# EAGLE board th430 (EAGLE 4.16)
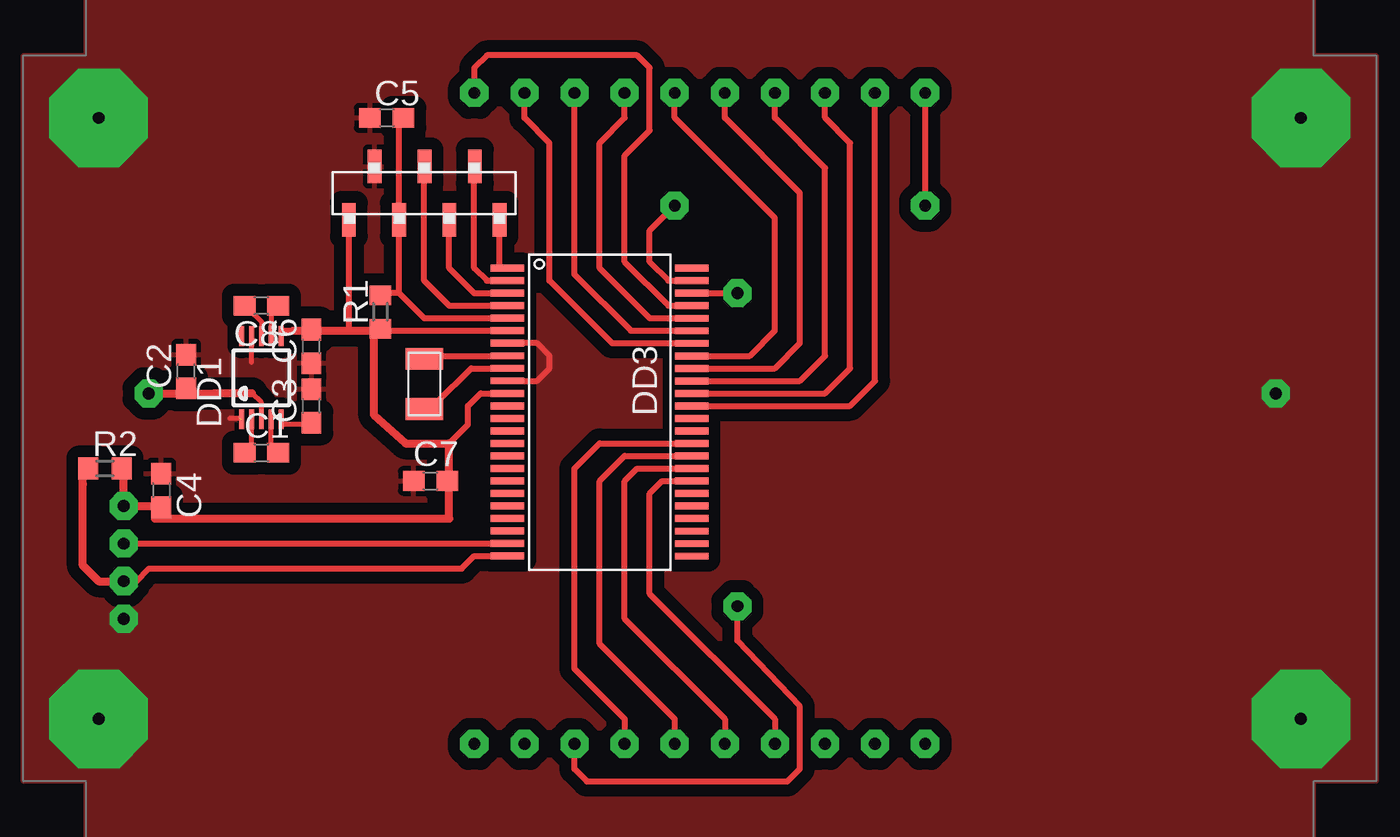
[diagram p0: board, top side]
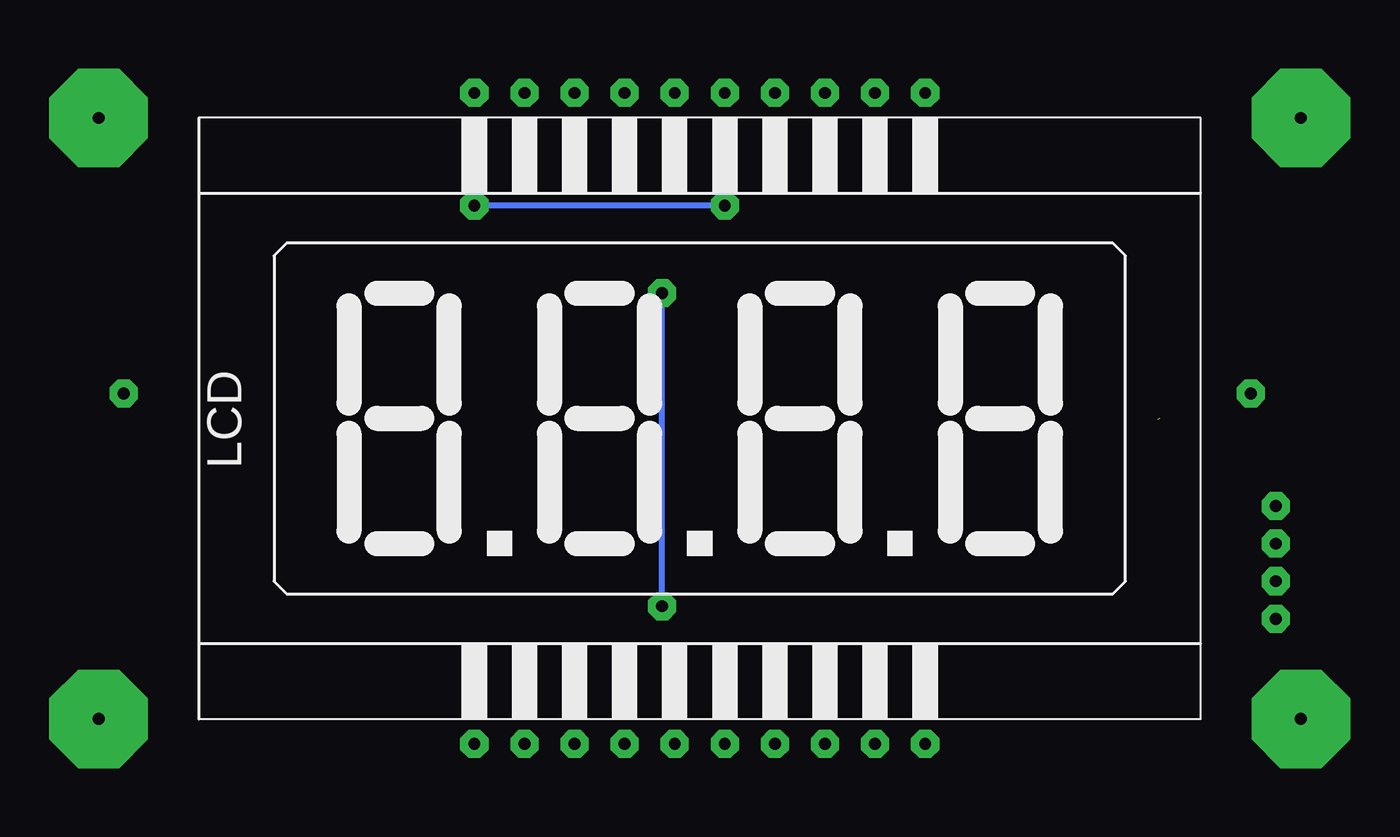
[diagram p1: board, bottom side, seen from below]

No outline drawn. Coordinates in mm, seen from the top.
Copper layers (1*16): Top 0.035mm / dielectric 1.5mm / Bottom 0.035mm
Design rules "default": minimum track width 10mil, minimum drill 24mil, track to track 8mil, track to pad 8mil, pad to pad 8mil, via to via 8mil, smd to smd 8mil, copper to edge 40mil, drill to drill 8mil, minimum pad ring 10mil, minimum via ring 8mil, stop-mask expansion 4mil, vias tented up to drill 0mil, thermal gap 10mil

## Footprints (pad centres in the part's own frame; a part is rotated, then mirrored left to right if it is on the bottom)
C0603 = smd 1.1 x 1: 1 -0.85,0; 2 0.85,0
MSOP10 = smd 0.25 x 1: 1 -1,-2.113; 2 -0.5,-2.113; 3 0,-2.113; 4 0.5,-2.113; 5 1,-2.113; 6 1,2.113; 7 0.5,2.113; 8 0,2.113; 9 -0.5,2.113; 10 -1,2.113
DL48 = smd 0.35 x 1.705: 1 -7.305,-4.67; 2 -6.67,-4.67; 3 -6.035,-4.67; 4 -5.4,-4.67; 5 -4.765,-4.67; 6 -4.13,-4.67; 7 -3.495,-4.67; 8 -2.86,-4.67; 9 -2.225,-4.67; 10 -1.59,-4.67; 11 -0.955,-4.67; 12 -0.32,-4.67; 13 0.315,-4.67; 14 0.95,-4.67; 15 1.585,-4.67; 16 2.22,-4.67; 17 2.855,-4.67; 18 3.49,-4.67; 19 4.125,-4.67; 20 4.76,-4.67; 21 5.395,-4.67; 22 6.03,-4.67; 23 6.665,-4.67; 24 7.3,-4.67; 25 7.305,4.67; 26 6.67,4.67; 27 6.035,4.67; 28 5.4,4.67; 29 4.765,4.67; 30 4.13,4.67; 31 3.495,4.67; 32 2.86,4.67; 33 2.225,4.67; 34 1.59,4.67; 35 0.955,4.67; 36 0.32,4.67; 37 -0.315,4.67; 38 -0.95,4.67; 39 -1.585,4.67; 40 -2.22,4.67; 41 -2.855,4.67; 42 -3.49,4.67; 43 -4.125,4.67; 44 -4.76,4.67; 45 -5.395,4.67; 46 -6.03,4.67; 47 -6.665,4.67; 48 -7.3,4.67
VIM404 = drill 0.6 pad 1.422 octagon: 1 -11.43,-16.51; 2 -8.89,-16.51; 3 -6.35,-16.51; 4 -3.81,-16.51; 5 -1.27,-16.51; 6 1.27,-16.51; 7 3.81,-16.51; 8 6.35,-16.51; 9 8.89,-16.51; 10 11.43,-16.51; 11 11.43,16.51; 12 8.89,16.51; 13 6.35,16.51; 14 3.81,16.51; 15 1.27,16.51; 16 -1.27,16.51; 17 -3.81,16.51; 18 -6.35,16.51; 19 -8.89,16.51; 20 -11.43,16.51
ABS07 = smd 1.1 x 1.9: 1 -1.27,0; 2 1.27,0
HEADER7S = smd 0.7 x 1.7: P$1 -1.27,1.35; P$2 1.28,1.35; P$3 -3.82,1.35; P$4 -2.57,-1.35; P$5 -0.02,-1.35; P$6 3.82,1.35; P$7 2.52,-1.35
R0603 = smd 1 x 1.1: 1 -0.85,0; 2 0.85,0

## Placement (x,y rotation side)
C1  [C0603]  12.06,19.84 0 top
C2  [C0603]  8.26,23.97 90 top
C3  [C0603]  14.61,22.22 90 top
C4  [C0603]  6.99,17.94 270 top
C5  [C0603]  18.41,36.83 0 top
C6  [C0603]  14.61,25.24 90 top
C7  [C0603]  20.64,18.41 0 top
C8  [C0603]  12.06,27.3 180 top
DD1  [MSOP10]  12.06,23.65 0 top
DD3  [DL48]  29.21,21.91 270 top
E$2  [VIM404]  34.29,21.59 0 bottom
E$11  [ABS07]  20.32,23.34 90 top
E$14  [HEADER7S]  20.32,33.02 180 top
R1  [R0603]  18.1,26.99 90 top
R2  [R0603]  4.13,19.05 0 top

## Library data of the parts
C1-C4 C6-C8 = ref-packages
C5 R1 R2 = smd-ipc
DD1 = analog-devices
DD3 = TI_MSP430_v122
E$2 = display-lcd
E$11 = crystal
E$14 = sb

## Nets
GND: C2.2 C3.2 C4.1 C5.1 C6.1 C7.1 DD1.1 E$14.P$7
S$6: E$2.8
S$13: E$2.11
S$35: E$2.20

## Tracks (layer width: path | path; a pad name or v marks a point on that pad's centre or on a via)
GND  (via drill 0.6 pad 1.42, 0.6 pad 5)  (1 unrouted)
  Top 0.254: 10.95,21.59 10.48,21.59 | 11.56,24.44 11.56,25.4
  Top 0.305: 25.08,25.4 26.04,25.4 26.67,24.77 26.67,24.13 26.04,23.5 24.77,23.5
  other vias: 5.08,11.43 63.5,22.86 3.81,36.83 3.81,6.35 64.77,6.35 64.77,36.83
  pour Top (isolate 0.61): 3.17,3.17 0,3.17 0,40.01 3.17,40.01 3.17,43.18 65.41,43.18 65.41,40.01 68.58,40.01 68.58,3.17 65.4,3.17 65.41,0 3.17,0
S$1
  Top 0.305: 5.08,13.34 5.71,13.34 6.35,13.97 22.23,13.97 22.86,14.61 24.13,14.61
S$2
  Top 0.305: 5.08,15.24 24.13,15.24
S$3  (via drill 0.6 pad 1.42)
  Top 0.406: v6.35,22.86 9.68,22.86
S$4
  Top 0.305: 21.59,31.75 21.59,29.21 22.86,27.94 24.13,27.94
S$5
  Top 0.305: 20.64,24.77 24.13,24.77
S$6
  Top 0.305: 36.2,12.06 36.2,10.32 39.37,6.99 39.37,3.81 38.73,3.17 28.57,3.17 27.94,3.81 E$2.8
S$7
  Top 0.305: 24.13,31.59 24.13,29.21 24.77,29.21
S$8  (via drill 0.6 pad 1.42)
  Top 0.406: 3.81,13.34 | 3.81,13.34 3.02,14.13 3.02,18.26 3.02,19.21 | 3.02,19.21 | 3.81,13.34 v5.08,13.34
S$9
  Top 0.305: 24.77,28.57 23.5,28.57 22.86,29.21 22.86,34.29
S$10
  Top 0.305: 20.32,34.29 20.32,28.57 21.59,27.3 24.77,27.3
S$11
  Top 0.305: 20.95,22.23 20.95,22.38 22.7,24.13 23.81,24.13
S$12
  Top 0.305: 21.59,20.32 22.54,21.27 22.54,22.23 23.18,22.86 23.81,22.86
  Top 0.406: 17.78,26.04 17.78,21.75 19.37,20.32 21.59,20.32
S$13
  Top 0.305: 33.34,27.3 32.7,27.3 30.48,29.53 30.48,34.92 31.75,36.2 31.75,39.37 31.11,40.01 23.5,40.01 22.86,39.37 E$2.11
S$14  (via drill 0.6 pad 1.42)
  other vias: 5.08,15.24
S$15  (via drill 0.6 pad 1.42)
  other vias: 33.02,32.38
S$16
  Top 0.305: 19.05,27.94 18.1,27.94 | 19.05,27.94 20.32,26.67 24.45,26.67 | 19.05,27.94 19.05,36.83
S$17  (via drill 0.6 pad 1.42)
  other vias: 36.2,27.94
S$18
  Top 0.305: 43.18,38.1 43.18,23.5 41.91,22.23 34.29,22.23
S$19
  Top 0.406: 5.08,17.14 5.08,19.05
S$20
  Top 0.305: 30.48,38.1 30.48,36.83 29.21,35.56 29.21,29.21 31.75,26.67 33.34,26.67
S$21
  Top 0.305: 40.64,38.1 40.64,36.83 41.91,35.56 41.91,24.13 40.64,22.86 34.29,22.86
S$22
  Top 0.305: 38.1,38.1 38.1,36.83 40.64,34.29 40.64,24.77 39.37,23.5 34.29,23.5
S$23
  Top 0.305: 34.29,24.13 38.1,24.13 39.37,25.4 39.37,33.02 35.56,36.83 35.56,38.1
S$24
  Top 0.305: 33.02,38.1 33.02,36.83 38.1,31.75 38.1,26.04 36.83,24.77 34.29,24.77
S$25
  Top 0.305: 33.02,5.08 33.02,6.35 29.21,10.16 29.21,18.41 30.48,19.68 33.34,19.68
S$26
  Top 0.305: 35.56,5.08 35.56,6.35 30.48,11.43 30.48,18.41 31.11,19.05 33.34,19.05
S$27
  Top 0.305: 17.62,26.04 24.77,26.04
  Top 0.406: 13.65,26.04 17.62,26.04
S$28
  Top 0.305: 34.29,20.32 29.21,20.32 27.94,19.05 27.94,8.89 30.48,6.35 30.48,5.08
S$29  (via drill 0.6 pad 1.42)
  other vias: 45.72,32.38
S$30
  Top 0.305: 38.1,5.08 38.1,6.35 31.75,12.7 31.75,17.78 32.38,18.41 33.34,18.41
S$31  (via drill 0.6 pad 1.42)
  other vias: 36.2,12.06
S$32
  Top 0.305: 33.02,28.57 32.7,28.57 31.75,29.53 31.75,31.11 33.02,32.38
S$33
  Top 0.305: 27.94,38.1 27.94,28.89 30.8,26.04 33.34,26.04
S$34
  Top 0.305: 34.29,27.94 36.2,27.94
S$35
  Top 0.305: 45.72,32.38 E$2.20
S$36
  Top 0.305: 25.4,38.1 25.4,36.83 26.67,35.56 26.67,28.57 29.84,25.4 33.34,25.4
S$37
  Bottom 0.305: 33.02,32.38 45.72,32.38
S$38
  Bottom 0.305: 36.2,12.06 36.2,27.94
S$39
  Top 0.254: 11.56,20.29 11.56,21.16
S$40
  Top 0.254: 12.56,20.22 12.57,21.14
S$41
  Top 0.254: 11.59,22.86 12.06,22.38 12.06,21.91
  Top 0.406: 11.59,22.86 9.68,22.86
S$42
  Top 0.254: 14.61,21.27 13.18,21.27
S$43
  Top 0.254: 14.61,26.04 13.18,26.04
S$44
  Top 0.254: 12.56,26.93 12.57,26.19
S$45
  Top 0.254: 12.06,26.19 12.06,26.51 11.43,27.15
S$46  (via drill 0.6 pad 1.42)
  Top 0.406: v5.08,17.14 6.67,17.14 6.67,16.51 21.59,16.51 21.59,20.32
S$47
  Top 0.305: 16.51,26.04 16.51,31.75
